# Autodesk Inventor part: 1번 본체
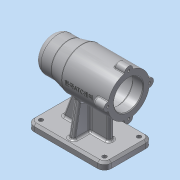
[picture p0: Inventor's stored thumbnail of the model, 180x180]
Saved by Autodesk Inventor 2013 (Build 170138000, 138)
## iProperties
Created: 2019-07
Part Number: 1번 본체
Material: 알루미늄 6061
Document SubType Name: Modeling
Designer: dgall
Density: 2.71 g/cm^3
Mass: 649.134 g
Surface Area: 655.8 cm^2
Volume: 239.533 cm^3
Author: dgall
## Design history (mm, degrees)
sketch "스케치1"
  geometry: L1 (-56, 35)-(56, 35); L2 (56, 35)-(56, -35); L3 (56, -35)-(-56, -35); L4 (-56, -35)-(-56, 35); 3 further points
  constraints: 8 end point, 2 midpoint, 2 parallel, 1 horizontal, 1 horizontal alignment, 1 perpendicular, 1 vertical alignment
  dimensions: "d0" = 112 distance of L1.start L1.end; "d1" = 70 distance of L3.end L1.start
extrude "돌출1" new body sketch "스케치1" distance "d2" = 10; taper "d3" = 0 deg
fillet "모깎기1" dims "d4" = 10
node "작업 평면1"
sketch "스케치2"
  geometry: L1 (-56, 80)-(56, 80); L2 (-56, 80)-(-56, 105); L3 (-56, 105)-(-31, 105); L4 (-31, 105)-(-11, 110); L5 (-11, 110)-(56, 110); L6 (56, 110)-(56, 80); 2 further points
  constraints: 12 end point, 3 horizontal, 2 vertical, 1 vertical alignment
  dimensions: "d6" = 112 distance of L1.start L1.end; "d7" = 80 distance from line of point (0, 0) L1; "d8" = 60 diameter of L5 L1; "d9" = 50 diameter of L3 L1; "d10" = 25 distance of L2.end L3.end; "d11" = 45 distance from line of L4.end L2
revolve "회전1" sketch "스케치2" stored, may be unused: angle "d12" = 90 deg
sketch "스케치3"
  geometry: L1 (-56, 55)-(-56, 105) reference; L2 (56, 50)-(56, 110) reference; L3 (-56, 80)-(56, 80); L4 (56, 101)-(41, 101); L5 (41, 101)-(41, 104); L6 (41, 104)-(-13, 104); L7 (-13, 104)-(-13, 101); L8 (-13, 101)-(-24.7, 101); L9 (-25, 100.7)-(-25, 97.5); L10 (-25, 97.5)-(-42.7, 97.5); L11 (-43, 97.2)-(-43, 96); L12 (-43, 96)-(-46.7, 96); L13 (-47, 95.7)-(-47, 90.5); L14 (-47, 90.5)-(-47, 90.5); L15 (-50, 87.5)-(-50, 80); L16 (56, 101)-(56, 80); A1 r 0.3 centre (-46.7, 95.7) between (-46.7, 96) and (-47, 95.7); A2 r 0.3 centre (-42.7, 97.2) between (-42.7, 97.5) and (-43, 97.2); A3 r 0.3 centre (-24.7, 100.7) between (-24.7, 101) and (-25, 100.7); A4 r 3 centre (-47, 87.5) between (-47, 90.5) and (-50, 87.5); 5 further points
  constraints: 28 end point, 10 point on line, 8 point on circle, 8 tangent, 6 vertical, 5 horizontal, 4 centre point, 2 equal radius, 2 midpoint, 2 perpendicular
  dimensions: "d13" = 42 diameter of L4 L3; "d15" = 48 diameter of L6 L3; "d16" = 42 diameter of L8 L3; "d17" = 35 diameter of L10 L3; "d18" = 32 diameter of L12 L3; "d19" = 21 diameter of L14 L3; "d20" = 3 distance of L13.end point (-50, 90.5); "d21" = 4 distance of L11.end point (-47, 96); "d22" = 18 distance of L9.end point (-43, 97.5); "d23" = 12 distance of L7.end point (-25, 101); "d24" = 54 distance of L5.end L6.end; "d25" = 15 distance of L4.start L4.end; "d26" = 0.3 radius of A1; "d27" = 3 radius of A4
revolve "회전2" sketch "스케치3" stored, may be unused: angle "d28" = 90 deg
fillet "모깎기2" dims "d29" = 3
sketch "스케치4"
  geometry: A1 r 30 centre (0, 0) between (-30, 0) and (-29.4, -5.97) reference; A2 r 6 centre (-30, 0) between (-29.4, 5.97) and (-29.4, -5.97); 1 further point
  constraints: 5 point on circle, 1 centre point
  dimensions: "d30" = 12 diameter of A2
extrude "돌출2" join sketch "스케치4" distance "d31" = 16; taper "d32" = 0 deg
fillet "모깎기3" dims "d36" = 10
fillet "모깎기4" dims "d37" = 3
sketch "스케치5"
  geometry: A1 r 6 centre (0, 0) between (0.6, 5.97) and (0.6, -5.97) reference; 2 further points
  constraints: 1 coincident
hole "구멍1" sketch "스케치5" at (0, 0) diameter "d38" = 3.242; stored, may be unused: countersink angle "d42" = 90 deg, drill point angle "d44" = 118 deg; dims "d39" = 8, "d40" = 4, "d41" = 2, "d43" = 11
fillet "모깎기5" dims "d48" = 3
fillet "모깎기6" dims "d49" = 1
fillet "모깎기7" dims "d50" = 3
fillet "모깎기8" dims "d51" = 1
chamfer "모따기1" distance "d52" = 1; stored, may be unused: second distance "d53" = 2, angle "d54" = 45 deg
sketch "스케치6"
  geometry: L1 (-46, 10)-(46, 10) reference; L2 (-56, 10)-(-46, 10) reference; L3 (-36, 10)-(-19.985, 54); L4 (-19.985, 54)-(31, 54); L5 (31, 54)-(31, 10); L6 (56, 10)-(56, 0) reference; L7 (-56, 0)-(-56, 10) reference; 1 further point
  constraints: 6 end point, 2 point on line, 1 horizontal, 1 vertical
  dimensions: "d55" = 25 distance between parallel lines of L6 L5; "d56" = 20 distance from line of L3.start L7; "d57" = 110 deg angle of L2 L3; "d58" = 54 distance from line of point (0, 0) L4
extrude "돌출3" join sketch "스케치6" stored distance "d59" = 8; taper "d60" = 0 deg
node "작업 평면2"
sketch "스케치7"
  geometry: L1 (-25, 10)-(25, 10) reference; L2 (25, 10)-(35, 10) reference; L3 (-35, 10)-(-25, 10) reference; L4 (-28, 10)-(-19.139, 60.253); L5 (28, 10)-(19.139, 60.253); L6 (-35, 0)-(-35, 10) reference; L7 (35, 10)-(35, 0) reference; C1 r 7.5 at (0, 80) reference; A1 r 27.5 centre (0, 80) between (-19.139, 60.253) and (19.139, 60.253); 1 further point
  constraints: 4 end point, 2 point on circle, 2 point on line, 1 centre point, 1 coincident
  dimensions: "d62" = 7 distance from line of L4.start L6; "d63" = 7 distance from line of L7 L5.start; "d64" = 100 deg angle of L2 L5; "d65" = 100 deg angle of L3 L4; "d66" = 55 diameter of A1
extrude "돌출4" join sketch "스케치7" stored distance "d67" = 8; taper "d68" = 0 deg
fillet "모깎기9" dims "d69" = 3
fillet "모깎기10" dims "d70" = 3
fillet "모깎기11" dims "d71" = 3
node "작업 평면3"
sketch "스케치9"
  geometry: L1 (33.5, 6.771)-(33.5, 29.226) reference; L2 (33.5, -5.998)-(33.5, 5.998) reference; 3 further points
  constraints: 1 horizontal alignment, 1 midpoint, 1 other
  dimensions: "d80" = 42 distance from line of L1 point (-8.5, 0)
feature "엠보싱1" sketch "스케치9" dims "d0" = 112, "d1" = 70, "d81" = 0.5, "d82" = 0
chamfer "모따기2" distance "d83" = 3; stored, may be unused: second distance "d84" = 2, angle "d85" = 45 deg
sketch "스케치10"
  geometry: A1 r 7 centre (46, -25) between (46, -32) and (53, -25) reference; A2 r 7 centre (46, 25) between (53, 25) and (46, 32) reference; A3 r 7 centre (-46, 25) between (-46, 32) and (-53, 25) reference; A4 r 7 centre (-46, -25) between (-53, -25) and (-46, -32) reference; 5 further points
  constraints: 4 coincident
hole "구멍3" sketch "스케치10" at (-46, 25), (46, 25), (-46, -25), (46, -25) diameter "d86" = 6; stored, may be unused: countersink angle "d90" = 90 deg, drill point angle "d92" = 118 deg; dims "d87" = 6, "d88" = 4, "d89" = 2, "d91" = 8
node "솔리드1"
pattern_circular "원형 패턴1" dims angle "d34" = 360 deg
pattern_circular "원형 패턴2" dims angle "d46" = 360 deg
other parameters: "d5" = 0, "d61" = 0
